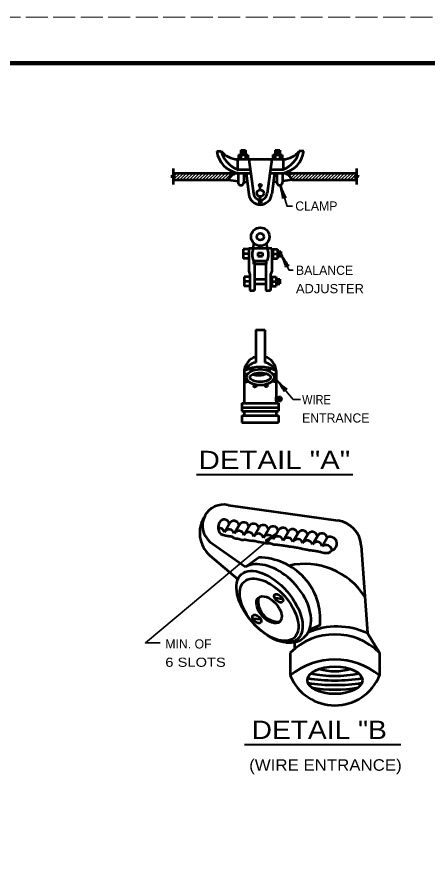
# Model space of a CAD drawing. Extents: x -286 to 394, y -156 to 284.
# Drawn here: x -126.2 to -36.6, y 96.5 to 284.5 of the extents above; entities that cross this region are included whole.
import ezdxf
from ezdxf.enums import TextEntityAlignment as Align

# ---------------------------------------------------------------- set-up
doc = ezdxf.new("R2010")
doc.units = 0
doc.header["$LTSCALE"] = 0.8
doc.linetypes.add('LONG_DASHED', pattern=[7.5, 6, -1.5])
doc.layers.add('1', color=7, linetype='Continuous', lineweight=53)
doc.layers.add('61', color=7, linetype='Continuous', lineweight=35)

msp = doc.modelspace()

# ---------------------------------------------------------------- hatches: boundary and pattern name
at = {"layer": '1'}
for points in [[(-74.7995, 207.5584, 1), (-75.2995, 207.5584, 1)], [(-72.924, 207.9139, 1), (-73.424, 207.9139, 1)], [(-71.0781, 207.5782, 1), (-71.5781, 207.5782, 1)], [(-76.0828, 206.4525, 1), (-76.5828, 206.4525, 1)], [(-75.905, 205.08, 1), (-76.405, 205.08, 1)], [(-69.8936, 205.159, 1), (-70.3936, 205.159, 1)], [(-69.7752, 206.4525, 1), (-70.2752, 206.4525, 1)], [(-74.0888, 204.0333, 1), (-74.5888, 204.0333, 1)], [(-71.6012, 204.0828, 1), (-72.1012, 204.0828, 1)]]:
    msp.add_hatch(color=256, dxfattribs=at).paths.add_polyline_path(points)
h = msp.add_hatch(color=256, dxfattribs=at)
edge = h.paths.add_edge_path()
edge.add_ellipse((-68.9269, 201.1685), major_axis=(0, -0.5), ratio=0.75, start_angle=0, end_angle=360)

# ---------------------------------------------------------------- linework, layer by layer
for p, q in [((-82.6702, 255.2281), (-81.6702, 255.2281)), ((-77.9202, 254.4781), (-75.9203, 254.4781)), ((-77.9202, 254.4781), (-77.9202, 253.4781)), ((-77.4202, 255.4781), (-77.4202, 253.4781)), ((-77.4202, 255.4781), (-76.4203, 255.4781)), ((-77.4202, 254.9781), (-76.4203, 254.9781)), ((-77.1702, 255.2281), (-76.6703, 255.2281)), ((-77.1702, 254.7281), (-76.6703, 254.7281)), ((-76.4203, 255.4781), (-76.4203, 253.4781)), ((-75.9203, 254.4781), (-75.9203, 253.4781)), ((-70.4202, 254.4781), (-68.4202, 254.4781)), ((-70.4202, 254.4781), (-70.4202, 253.4781)), ((-69.9202, 255.4781), (-69.9202, 253.4781)), ((-69.9202, 255.4781), (-68.9202, 255.4781)), ((-69.9202, 254.9781), (-68.9202, 254.9781)), ((-69.6702, 255.2281), (-69.1702, 255.2281)), ((-69.6702, 254.7281), (-69.1702, 254.7281)), ((-68.9202, 255.4781), (-68.9202, 253.4781)), ((-68.4202, 254.4781), (-68.4202, 253.4781)), ((-63.6702, 255.2281), (-64.6702, 255.2281)), ((-78.1702, 253.4781), (-78.1702, 251.2281)), ((-75.6703, 253.4781), (-74.6702, 245.9772)), ((-70.6702, 253.4781), (-71.6702, 245.9772)), ((-68.1702, 253.4781), (-68.1702, 251.2281)), ((-92.1702, 249.9781), (-92.6702, 249.7281)), ((-92.1702, 251.4781), (-92.1702, 249.9781)), ((-92.1702, 250.4781), (-78.1702, 250.4781)), ((-78.0292, 250.4781), (-78.5273, 250.4345)), ((-78.1702, 251.2281), (-75.3703, 251.2281)), ((-78.1702, 250.4781), (-75.2703, 250.4781)), ((-78.0292, 250.4781), (-78.0292, 248.4781)), ((-76.7792, 250.4781), (-76.7792, 248.4781)), ((-76.2792, 250.4781), (-75.6615, 245.8452)), ((-71.0702, 250.4781), (-68.1702, 250.4781)), ((-70.9702, 251.2281), (-68.1702, 251.2281)), ((-70.0615, 250.4781), (-70.6791, 245.8452)), ((-69.5615, 250.4781), (-69.5615, 248.4781)), ((-68.3115, 250.4781), (-68.3115, 248.4781)), ((-68.3081, 250.4781), (-67.81, 250.4345)), ((-68.1702, 250.4781), (-52.1702, 250.4781)), ((-52.1403, 251.4412), (-52.1403, 249.9412)), ((-92.6702, 249.7281), (-91.6702, 249.7281)), ((-91.6702, 249.7281), (-92.1702, 249.4781)), ((-92.1702, 249.4781), (-92.1702, 247.9781)), ((-92.1702, 248.9781), (-80.1702, 248.9781)), ((-80.1702, 248.9781), (-78.0292, 248.7295)), ((-76.7792, 248.5844), (-76.0149, 248.4957)), ((-69.5615, 248.5843), (-70.3257, 248.4957)), ((-66.1702, 248.9781), (-68.3115, 248.7295)), ((-66.1702, 248.9781), (-52.1702, 248.9781)), ((-51.6403, 249.6912), (-52.6403, 249.6912)), ((-52.6403, 249.6912), (-52.1403, 249.4412)), ((-52.1403, 249.9412), (-51.6403, 249.6912)), ((-52.1403, 249.4412), (-52.1403, 247.9412)), ((-73.1702, 246.8291), (-73.1702, 247.5671)), ((-73.1702, 244.3297), (-73.1702, 245.3291)), ((-74.6702, 234.0782), (-74.5758, 235.1577)), ((-71.6702, 234.0782), (-71.7639, 235.1482)), ((-75.6702, 233.8282), (-76.9202, 233.8282)), ((-76.9202, 233.8282), (-76.9202, 231.8282)), ((-75.6702, 234.0782), (-70.6702, 234.0782)), ((-75.6702, 234.0782), (-75.6702, 229.0782)), ((-73.6702, 233.0782), (-72.6702, 233.0782)), ((-73.6702, 233.0782), (-73.6702, 232.3282)), ((-72.6702, 233.0782), (-72.6702, 232.3282)), ((-70.6702, 234.0782), (-70.6702, 229.0782)), ((-70.6702, 233.8282), (-69.4202, 233.8282)), ((-70.4202, 233.8282), (-70.4202, 231.8282)), ((-69.4202, 233.8282), (-69.4202, 231.8282)), ((-69.4202, 233.3282), (-68.6702, 233.3282)), ((-69.2327, 233.0782), (-69.2327, 232.5782)), ((-69.0452, 233.3282), (-69.0452, 232.3282)), ((-68.8577, 233.0782), (-68.8577, 232.5782)), ((-68.6702, 233.3282), (-68.6702, 232.3282)), ((-75.6702, 232.8282), (-76.9202, 232.8282)), ((-75.6702, 231.8282), (-76.9202, 231.8282)), ((-74.6702, 231.3282), (-71.6702, 231.3282)), ((-74.5452, 230.5782), (-74.5452, 231.3282)), ((-74.4933, 230.5782), (-74.4933, 231.3282)), ((-74.4933, 230.5782), (-74.4933, 231.3282)), ((-74.4703, 230.5782), (-74.4703, 231.3282)), ((-74.4703, 230.5782), (-74.4703, 231.3282)), ((-74.4246, 230.5782), (-74.4246, 231.3282)), ((-74.4202, 231.3282), (-74.4202, 224.8282)), ((-73.6702, 232.3282), (-72.6702, 232.3282)), ((-71.9202, 231.3282), (-71.9202, 224.8282)), ((-71.8727, 230.5782), (-71.8727, 231.3282)), ((-71.8612, 230.5782), (-71.8612, 231.3282)), ((-71.8383, 230.5782), (-71.8383, 231.3282)), ((-71.8268, 230.5782), (-71.8268, 231.3282)), ((-71.8154, 230.5782), (-71.8154, 231.3282)), ((-71.7952, 230.5782), (-71.7952, 231.3282)), ((-70.6702, 231.8282), (-69.4202, 231.8282)), ((-70.4202, 232.8282), (-69.4202, 232.8282)), ((-69.4202, 232.3282), (-68.6702, 232.3282)), ((-74.5452, 230.6379), (-71.7952, 230.6379)), ((-75.4489, 227.7935), (-76.6989, 227.7935)), ((-76.6989, 227.7935), (-76.6989, 225.7935)), ((-75.6702, 229.0782), (-75.4202, 228.3282)), ((-75.4202, 228.3282), (-75.4202, 224.8282)), ((-70.6702, 229.0782), (-70.9202, 228.3282)), ((-70.9202, 228.3282), (-70.9202, 224.8282)), ((-70.9202, 227.7935), (-69.6702, 227.7935)), ((-70.6702, 227.7935), (-70.6702, 225.7935)), ((-69.6702, 227.7935), (-69.6702, 225.7935)), ((-75.4489, 226.7935), (-76.6989, 226.7935)), ((-75.4489, 225.7935), (-76.6989, 225.7935)), ((-74.4202, 227.2935), (-71.9202, 227.2935)), ((-74.4202, 226.2935), (-71.9202, 226.2935)), ((-70.9202, 225.7935), (-69.6702, 225.7935)), ((-70.6702, 226.7935), (-69.6702, 226.7935)), ((-69.6702, 227.2935), (-68.9202, 227.2935)), ((-69.6702, 226.2935), (-68.9202, 226.2935)), ((-69.4827, 227.0435), (-69.4827, 226.5435)), ((-69.2952, 227.2935), (-69.2952, 226.2935)), ((-69.1077, 227.0435), (-69.1077, 226.5435)), ((-68.9202, 227.2935), (-68.9202, 226.2935)), ((-75.4202, 224.8282), (-74.4202, 224.8282)), ((-71.9202, 224.8282), (-70.9202, 224.8282)), ((-74.1702, 216.2935), (-72.1702, 216.2935)), ((-74.1702, 216.2935), (-74.1702, 209.1685)), ((-72.1702, 216.2935), (-72.1702, 209.1685)), ((-76.6702, 207.2935), (-76.6702, 200.2935)), ((-69.6702, 207.2935), (-69.6702, 201.5435)), ((-77.1702, 200.2935), (-69.1702, 200.2935)), ((-77.1702, 200.2935), (-77.1702, 198.5435)), ((-77.1702, 199.2935), (-69.1702, 199.2935)), ((-69.6702, 200.7935), (-69.6702, 200.2935)), ((-69.1702, 200.2935), (-69.1702, 198.5435)), ((-77.1702, 198.5435), (-69.1702, 198.5435)), ((-77.1702, 197.5435), (-69.1702, 197.5435)), ((-77.1702, 197.5435), (-77.1702, 196.0435)), ((-76.6702, 198.5435), (-76.6702, 197.5435)), ((-69.6702, 198.5435), (-69.6702, 197.5435)), ((-69.1702, 197.5435), (-69.1702, 196.0435)), ((-77.1702, 196.0435), (-69.1702, 196.0435)), ((-80.1702, 178.0435), (-56.264, 174.6838)), ((-81.0054, 172.102), (-79.9269, 173.9701)), ((-78.8694, 171.8018), (-77.7909, 173.6698)), ((-76.7333, 171.5016), (-75.6548, 173.3697)), ((-74.5973, 171.2014), (-73.5187, 173.0695)), ((-72.4612, 170.9013), (-71.3828, 172.7692)), ((-70.3252, 170.601), (-69.2467, 172.4691)), ((-68.1891, 170.3008), (-67.1106, 172.1688)), ((-66.0531, 170.0006), (-64.9746, 171.8687)), ((-63.917, 169.7004), (-62.8385, 171.5685)), ((-61.7809, 169.4002), (-60.7024, 171.2682)), ((-84.1702, 170.0435), (-76.3883, 164.5945)), ((-59.6449, 169.1), (-58.5663, 170.9681)), ((-51.1137, 169.1606), (-49.7783, 150.066)), ((-84.1702, 167.0435), (-78.0419, 161.9012)), ((-76.3883, 164.5945), (-73.5213, 166.602)), ((-69.9634, 157.7752), (-68.3375, 157.6078)), ((-74.7455, 153.3264), (-73.0957, 153.159)), ((-60.1191, 151.8091), (-62.4427, 150.8167)), ((-65.6288, 146.7224), (-65.6288, 148.154)), ((-66.6288, 145.8257), (-66.6288, 140.8257))]:
    msp.add_line(p, q, dxfattribs=at)
at = {"layer": '1', "lineweight": 25}
for p, q in [((-92.1702, 248.9781), (-90.6702, 250.4781)), ((-92.1274, 249.7281), (-91.3774, 250.4781)), ((-91.4633, 248.9781), (-89.9633, 250.4781)), ((-90.7561, 248.9781), (-89.2561, 250.4781)), ((-90.0491, 248.9781), (-88.5491, 250.4781)), ((-89.3419, 248.9781), (-87.8419, 250.4781)), ((-88.6347, 248.9781), (-87.1347, 250.4781)), ((-87.9278, 248.9781), (-86.4278, 250.4781)), ((-87.2206, 248.9781), (-85.7206, 250.4781)), ((-86.5134, 248.9781), (-85.0134, 250.4781)), ((-85.8064, 248.9781), (-84.3064, 250.4781)), ((-85.0992, 248.9781), (-83.5992, 250.4781)), ((-84.3923, 248.9781), (-82.8923, 250.4781)), ((-83.6851, 248.9781), (-82.1851, 250.4781)), ((-82.9779, 248.9781), (-81.4779, 250.4781)), ((-82.2709, 248.9781), (-80.7709, 250.4781)), ((-81.5639, 248.9781), (-80.0639, 250.4781)), ((-80.8567, 248.9781), (-79.3567, 250.4781)), ((-67.1713, 250.0985), (-66.7917, 250.4781)), ((-66.7799, 249.7827), (-66.0846, 250.4781)), ((-66.4451, 249.4104), (-65.3774, 250.4781)), ((-66.1702, 248.9781), (-64.6702, 250.4781)), ((-65.4633, 248.9781), (-63.9632, 250.4781)), ((-64.7561, 248.9781), (-63.2561, 250.4781)), ((-64.0491, 248.9781), (-62.5491, 250.4781)), ((-63.3419, 248.9781), (-61.8419, 250.4781)), ((-62.6347, 248.9781), (-61.1347, 250.4781)), ((-61.9277, 248.9781), (-60.4277, 250.4781)), ((-61.2207, 248.9781), (-59.7207, 250.4781)), ((-60.5136, 248.9781), (-59.0136, 250.4781)), ((-59.8066, 248.9781), (-58.3066, 250.4781)), ((-59.0994, 248.9781), (-57.5994, 250.4781)), ((-58.3922, 248.9781), (-56.8922, 250.4781)), ((-57.6852, 248.9781), (-56.1852, 250.4781)), ((-56.9781, 248.9781), (-55.4781, 250.4781)), ((-56.2711, 248.9781), (-54.7711, 250.4781)), ((-55.5639, 248.9781), (-54.0639, 250.4781)), ((-54.8569, 248.9781), (-53.3569, 250.4781)), ((-54.1497, 248.9781), (-52.6497, 250.4781)), ((-53.4426, 248.9781), (-52.1403, 250.2804)), ((-52.7356, 248.9781), (-52.2283, 249.4853))]:
    msp.add_line(p, q, dxfattribs=at)
at = {"layer": '1', "lineweight": 40}
for p, q in [((-87.0957, 184.7409), (-52.9591, 184.7409)), ((-76.6281, 125.8264), (-42.4914, 125.8264))]:
    msp.add_line(p, q, dxfattribs=at)
at = {"layer": '1'}
for points in [[(-78.1702, 253.4781), (-75.6703, 253.4781), (-70.6702, 253.4781), (-68.1702, 253.4781)], [(-49.7784, 150.066), (-47.1288, 145.8257), (-47.1288, 140.8257)]]:
    msp.add_lwpolyline(points, dxfattribs=at)
at = {"layer": '1', "lineweight": 35}
for points in [[(-68.7868, 247.7581), (-67.329, 243.2409), (-66.1423, 243.2409)], [(-68.5735, 232.6772), (-66.8312, 229.2627), (-65.9653, 229.2627)], [(-69.5265, 205.2583), (-65.9578, 201.0998), (-64.3885, 201.0998)], [(-69.6575, 171.8985), (-98.2464, 147.9543), (-95.0018, 147.9543)]]:
    msp.add_lwpolyline(points, dxfattribs=at)
at = {"layer": '1'}
msp.add_lwpolyline([(-69.6702, 200.7935), (-69.6702, 201.5435), (-69.1702, 201.5435), (-69.1702, 200.7935)], close=True, dxfattribs=at)
for centre, radius in [((-73.1696, 246.0791), 0.75), ((-73.1747, 247.8171), 0.25), ((-73.1747, 244.0797), 0.25), ((-73.1651, 236.5753), 2), ((-73.1651, 236.5753), 0.75), ((-75.0495, 207.5584), 0.25), ((-73.174, 207.9139), 0.25), ((-71.3281, 207.5782), 0.25), ((-76.3328, 206.4525), 0.25), ((-76.155, 205.08), 0.25), ((-70.1436, 205.159), 0.25), ((-70.0252, 206.4525), 0.25), ((-74.3388, 204.0333), 0.25), ((-71.8512, 204.0828), 0.25)]:
    msp.add_circle(centre, radius, dxfattribs=at)
for centre, radius, start, end in [((-77.1277, 255.9724), 5.5923, 187.64817, 259.25551), ((-78.0027, 258.1882), 4.7131, 218.90739, 267.9625), ((-75.9957, 256.662), 5.8529, 194.18169, 248.19017), ((-69.1952, 255.9724), 5.5923, 280.74449, 352.35183), ((-68.3202, 258.1882), 4.7131, 272.0375, 321.09261), ((-70.3271, 256.662), 5.8529, 291.80983, 345.81831), ((-77.1513, 247.2274), 3.4899, 113.22226, 149.89059), ((-68.9481, 247.4958), 3.1514, 28.05788, 68.82928), ((-77.4042, 248.4354), 0.6264, 176.096, 3.904), ((-68.9365, 248.4354), 0.6264, 176.096, 3.904), ((-73.1703, 246.0805), 2.5023, 185.3956, 354.6044), ((-73.1702, 246.0818), 1.5036, 183.98846, 356.01154), ((-71.3926, 232.7032), 3.5544, 157.24187, 202.75812), ((-74.8382, 232.7032), 3.4535, 336.53763, 23.46238), ((-73.1702, 207.0339), 3.5096, 106.55476, 175.75781), ((-73.1702, 205.231), 4.0625, 104.25003, 149.48976), ((-73.1702, 207.0339), 3.5096, 4.24219, 73.44524), ((-73.1702, 205.231), 4.0625, 30.51024, 75.74997), ((-73.1702, 200.731), 7.4375, 61.92751, 118.07249), ((-73.4954, 210.114), 3.767, 249.21209, 295.95947), ((-81.1801, 173.5484), 4.6071, 77.33852, 229.53137), ((-79.7822, 171.9799), 6.6048, 146.67294, 228.36581), ((-81.0488, 173.7367), 1.1459, 11.75001, 152.2471), ((-80.2237, 173.1616), 2.1475, 148.91645, 220.4444), ((-82.1273, 171.8686), 1.1459, 11.75001, 101.93956), ((-78.9128, 173.4365), 1.1459, 11.75001, 152.2471), ((-76.7768, 173.1362), 1.1459, 11.75001, 152.2471), ((-74.6407, 172.8361), 1.1459, 11.75001, 152.2471), ((-72.5047, 172.5359), 1.1459, 11.75001, 152.2471), ((-70.3687, 172.2356), 1.1459, 11.75001, 152.2471), ((-68.2326, 171.9355), 1.1459, 11.75001, 152.2471), ((-57.0991, 168.7421), 6, 3.99951, 81.99965), ((-79.9913, 171.5684), 1.1459, 11.75001, 152.2471), ((-77.8553, 171.2682), 1.1459, 11.75001, 152.2471), ((-75.7192, 170.968), 1.1459, 11.75001, 152.2471), ((-73.5832, 170.6678), 1.1459, 11.75001, 152.2471), ((-71.4472, 170.3676), 1.1459, 11.75001, 152.2471), ((-69.3111, 170.0674), 1.1459, 11.75001, 152.2471), ((-66.0965, 171.6352), 1.1459, 11.75001, 152.2471), ((-63.9605, 171.3351), 1.1459, 11.75001, 152.2471), ((-61.8244, 171.0349), 1.1459, 11.75001, 152.2471), ((-59.6883, 170.7346), 1.1459, 11.75001, 152.2471), ((-57.9414, 169.6023), 1.502, 287.78042, 114.58588), ((-67.175, 169.7672), 1.1459, 11.75001, 152.2471), ((-65.039, 169.467), 1.1459, 11.75001, 152.2471), ((-62.9029, 169.1668), 1.1459, 11.75001, 152.2471), ((-60.7668, 168.8666), 1.1459, 11.75001, 152.2471), ((-58.9021, 167.848), 1.4558, 12.8606, 120.68146), ((-73.6008, 153.0624), 13.5399, 354.68901, 89.66358), ((-63.444, 149.6147), 15.5854, 32.75237, 102.73689), ((-69.1472, 157.0836), 4.4942, 170.61826, 272.91325), ((-56.4348, 135.755), 15.7833, 65.05583, 113.43858), ((-56.8788, 135.9429), 13.8828, 45.38759, 134.61241), ((-56.8788, 128.9954), 15.3304, 50.50632, 129.49367), ((-56.8788, 170.4488), 29.6602, 259.76655, 280.23345), ((-56.8788, 153.7766), 11.988, 253.39383, 286.60618), ((-56.8788, 144.8882), 10.5625, 202.61986, 337.38013), ((-56.8788, 177.7468), 37.9582, 260.99995, 279.00005), ((-56.8788, 176.4852), 37.6966, 261.0124, 278.9876), ((-56.8788, 166.4136), 28.625, 259.73317, 280.26683)]:
    msp.add_arc(centre, radius, start, end, dxfattribs=at)
at = {"layer": '1', "lineweight": 40}
for centre, major_axis, ratio, start_param, end_param in [((-68.6441, 246.6268), (0.3723, -1.7255), 0.07063, 6.28230741, 8.55970261), ((-68.1887, 246.8045), (-0.697, 1.6514), 0.122415, 0.89635335, 3.14159265), ((-68.2527, 231.583), (0.6419, -1.6444), 0.07063, 6.28230741, 8.55970261), ((-67.8314, 231.8308), (-0.9507, 1.5196), 0.122415, 0.89635335, 3.14159265), ((-68.9573, 204.2701), (1.0106, -1.4473), 0.07063, 6.28230741, 8.55970261), ((-68.6062, 204.6101), (-1.2814, 1.2534), 0.122415, 0.89635335, 3.14159265), ((-70.6524, 171.3413), (-1.4593, -0.9931), 0.07063, 6.28230741, 8.55970261), ((-70.3166, 170.986), (1.2687, 1.2663), 0.122415, 0.89635335, 3.14159265)]:
    msp.add_ellipse(centre, major_axis=major_axis, ratio=ratio, start_param=start_param, end_param=end_param, dxfattribs=at)
at = {"layer": '1'}
for centre, major_axis, ratio in [((-73.1702, 205.9185), (-3, 0), 0.583333), ((-73.1702, 205.9185), (-2.25, 0), 0.444444), ((-68.9269, 201.1685), (0, -0.5), 0.75), ((-71.1411, 155.8661), (6.1224, -7.0785), 0.541131), ((-71.2501, 155.2057), (5.4588, -6.1127), 0.549098), ((-71.2501, 155.2057), (2.3312, -2.6105), 0.571425), ((-69.1624, 157.7035), (0.8727, -0.7654), 0.559667), ((-73.9205, 153.1829), (0.8727, -0.7654), 0.559667), ((-56.8788, 139.8257), (6, 0), 0.5)]:
    msp.add_ellipse(centre, major_axis=major_axis, ratio=ratio, dxfattribs=at)
msp.add_ellipse((-70.4047, 156.5869), major_axis=(6.916, -7.3487), ratio=0.63331, start_param=5.65532628, end_param=9.24694428, dxfattribs=at)
msp.add_spline([(-81.8674, 171.7719), (-81.1757, 171.5144), (-80.386, 171.3321), (-79.9303, 171.2713), (-79.2621, 171.1194), (-79.1102, 170.9978), (-78.3204, 170.7243), (-78.1078, 170.7243), (-77.2269, 170.4509), (-76.832, 170.4812), (-76.103, 170.4509), (-75.4651, 170.299), (-75.0398, 170.2686), (-74.5538, 170.2686), (-74.0375, 170.1471), (-73.6426, 170.0255), (-73.3388, 169.9951), (-72.6402, 169.904), (-72.2149, 169.8128), (-71.6377, 169.7217), (-71.0302, 169.6912), (-70.1797, 169.4482), (-70.0278, 169.4178), (-69.7545, 169.4178), (-69.2685, 169.3874), (-68.6306, 169.3267), (-68.0838, 169.2355), (-67.1726, 169.0836), (-66.7777, 169.0228), (-66.079, 168.962), (-65.8664, 168.9013), (-65.5627, 168.8405), (-65.0159, 168.7493), (-64.4995, 168.6582), (-63.8008, 168.4758), (-63.1326, 168.3543), (-62.3124, 168.2023), (-61.7353, 168.1416), (-61.2189, 168.0808), (-60.3987, 167.9289), (-60.1254, 167.8682), (-59.4875, 167.7162), (-58.9712, 167.5947), (-58.5458, 167.5947), (-58.2421, 167.6251), (-57.7561, 167.9592), (-57.3165, 168.2364)], degree=3, dxfattribs=at)
at = {"layer": '61', "linetype": 'LONG_DASHED', "lineweight": 13}
msp.add_line((-286.3491, 284.4627), (393.6709, 284.4627), dxfattribs=at)
at = {"layer": '61', "lineweight": 158}
msp.add_lwpolyline([(382.6909, 274.4627), (-256.3491, 274.4627), (-256.3491, -145.5572)], dxfattribs=at)

# ---------------------------------------------------------------- texts
at = {"layer": '1'}
msp.add_text('CLAMP', height=2, dxfattribs=at).set_placement((-60.9289, 242.2765), align=Align.CENTER)
for s, p in [('BALANCE', (-65.3734, 228.2587)), ('ENTRANCE', (-64.0361, 196.0413)), ('MIN. OF', (-93.8999, 146.7505))]:
    msp.add_text(s, height=2, dxfattribs=at).set_placement(p)
for s, width, p in [('ADJUSTER', 1.05, (-65.3734, 224.2587)), ('WIRE', 0.9, (-64.0361, 200.0413)), ('6 SLOTS', 1.2, (-93.8999, 142.7505))]:
    msp.add_text(s, height=2, dxfattribs=dict(at, width=width)).set_placement(p)
for s, height, width, p in [('DETAIL "A"', 4, 1.2, (-70.0755, 185.8793)), ('DETAIL "B', 4, 1.15, (-60.2981, 127.0087)), ('(WIRE ENTRANCE)', 2.5, 1.1, (-58.9363, 120.0828))]:
    msp.add_text(s, height=height, dxfattribs=dict(at, width=width)).set_placement(p, align=Align.CENTER)

doc.saveas('drawing.dxf')
